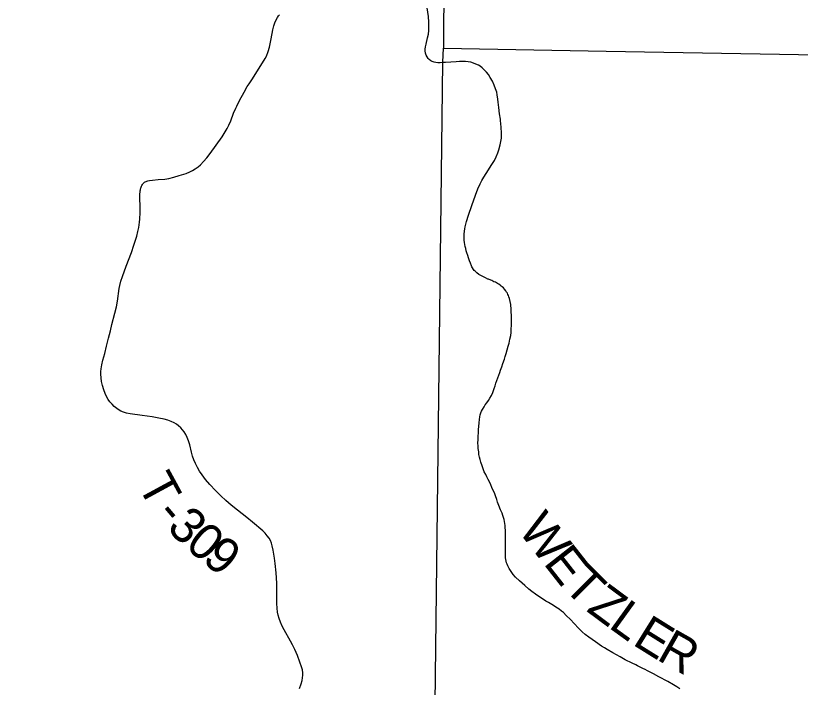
# Model space of a CAD drawing. Extents: x -10 to 158, y 8 to 33.
# Drawn here: x 127.727 to 128.969, y 27.363 to 28.427 of the extents above; entities that cross this region are included whole.
import ezdxf

# ---------------------------------------------------------------- set-up
doc = ezdxf.new("R2010")
doc.units = 0
for name, color, linetype in [('GM_X_Township_Road', 7, 'Continuous'), ('GM_X_Township_Road_Text', 7, 'Continuous'), ('GM_X_Township_Text', 7, 'Continuous')]:
    doc.layers.add(name, color=color, linetype=linetype)

msp = doc.modelspace()

# ---------------------------------------------------------------- linework, layer by layer
at = {"layer": 'GM_X_Township_Road'}
for points in [[(128.4044, 28.353), (128.4034, 28.353), (128.3993, 28.3526), (128.3956, 28.3526), (128.3925, 28.3529), (128.3895, 28.3535), (128.3865, 28.3546), (128.3843, 28.3557), (128.3819, 28.3576), (128.3801, 28.3593), (128.3784, 28.3619), (128.377, 28.3647), (128.3761, 28.3676), (128.3755, 28.3713), (128.3754, 28.3744), (128.3758, 28.3781), (128.3767, 28.3823), (128.3792, 28.3919), (128.3804, 28.398), (128.381, 28.4035), (128.3813, 28.4097), (128.3811, 28.4171), (128.3804, 28.4257), (128.3786, 28.4398)], [(128.1761, 27.3614), (128.1789, 27.3689), (128.1805, 27.3743), (128.1813, 27.3786), (128.1817, 27.3829), (128.1816, 27.3866), (128.1809, 27.3909), (128.1797, 27.3957), (128.1771, 27.4033), (128.1732, 27.4137), (128.169, 27.4233), (128.1655, 27.4305), (128.1622, 27.4365), (128.1518, 27.4542), (128.1487, 27.4602), (128.146, 27.4665), (128.1439, 27.4724), (128.1424, 27.4778), (128.1415, 27.4826), (128.1408, 27.4888), (128.1404, 27.4963), (128.1406, 27.5099), (128.1405, 27.5279), (128.1401, 27.5366), (128.1394, 27.5446), (128.1378, 27.5594), (128.1366, 27.568), (128.1347, 27.5809), (128.1332, 27.5876), (128.1319, 27.5918), (128.1302, 27.5958), (128.1281, 27.5996), (128.1253, 27.6036), (128.122, 27.6074), (128.118, 27.6113), (128.1019, 27.6248), (128.0929, 27.6322), (128.0779, 27.6442), (128.0682, 27.6519), (128.0597, 27.6591), (128.0516, 27.6668), (128.0433, 27.6752), (128.0345, 27.6848), (128.0277, 27.6928), (128.0224, 27.6997), (128.0182, 27.7059), (128.0147, 27.7117), (128.0116, 27.7178), (128.0092, 27.7235), (128.0071, 27.7294), (128.0054, 27.736), (128.0025, 27.7475), (128.0005, 27.754), (127.9985, 27.7592), (127.9964, 27.7637), (127.9938, 27.7679), (127.9912, 27.7714), (127.9882, 27.7746), (127.9849, 27.7775), (127.9814, 27.78), (127.9777, 27.7822), (127.9732, 27.7843), (127.968, 27.7863), (127.962, 27.7881), (127.9535, 27.7899), (127.9431, 27.7918), (127.9271, 27.7941), (127.9081, 27.7968), (127.9021, 27.7978), (127.8974, 27.7991), (127.8935, 27.8008), (127.8905, 27.8026), (127.8869, 27.8051), (127.883, 27.8082), (127.8795, 27.8117), (127.8762, 27.8154), (127.8734, 27.8195), (127.8709, 27.8238), (127.8686, 27.8289), (127.8664, 27.8347), (127.8645, 27.8412), (127.863, 27.8477), (127.8621, 27.8538), (127.8616, 27.8593), (127.8615, 27.8636), (127.862, 27.8678), (127.8633, 27.8743), (127.8651, 27.8815), (127.8678, 27.8922), (127.8708, 27.9036), (127.8739, 27.9163), (127.8769, 27.9283), (127.8793, 27.938), (127.8839, 27.956), (127.8863, 27.9662), (127.8879, 27.9748), (127.8909, 27.9951), (127.8918, 28), (127.8935, 28.0066), (127.8959, 28.0143), (127.902, 28.0306), (127.91, 28.0521), (127.9141, 28.0638), (127.9186, 28.078), (127.9205, 28.0852), (127.9219, 28.0919), (127.9231, 28.0999), (127.9234, 28.1049), (127.9236, 28.1079), (127.9238, 28.1123), (127.9239, 28.121), (127.9236, 28.1426), (127.9237, 28.1452), (127.9239, 28.1475), (127.9239, 28.1485), (127.9241, 28.1497), (127.9243, 28.1512), (127.9246, 28.1527), (127.9251, 28.1542), (127.9255, 28.1557), (127.9261, 28.157), (127.9268, 28.1584), (127.9276, 28.1598), (127.9284, 28.1609), (127.9293, 28.162), (127.9301, 28.1628), (127.9311, 28.1635), (127.9321, 28.1642), (127.9333, 28.1647), (127.9344, 28.1651), (127.936, 28.1656), (127.939, 28.1662), (127.9433, 28.1667), (127.9526, 28.1675), (127.9631, 28.1684), (127.9692, 28.1695), (127.9771, 28.1714), (127.986, 28.174), (127.9967, 28.1774), (128.0024, 28.1797), (128.0069, 28.182), (128.0111, 28.1846), (128.0156, 28.1879), (128.0193, 28.1912), (128.0242, 28.196), (128.0295, 28.2021), (128.0348, 28.209), (128.0443, 28.222), (128.0536, 28.2352), (128.0587, 28.243), (128.0618, 28.2483), (128.0645, 28.2539), (128.0674, 28.2607), (128.072, 28.2727), (128.0755, 28.2806), (128.077, 28.284), (128.0813, 28.2928), (128.0887, 28.3063), (128.0937, 28.3148), (128.0966, 28.3195), (128.1007, 28.3257), (128.115, 28.3482), (128.1218, 28.3594), (128.1239, 28.3631), (128.1269, 28.3706), (128.1287, 28.3772), (128.1315, 28.3905), (128.1341, 28.4046), (128.1358, 28.4112), (128.1374, 28.4159), (128.1394, 28.4205), (128.1415, 28.4243), (128.1433, 28.4268), (128.1449, 28.4287)], [(128.7786, 27.361), (128.7739, 27.3641), (128.7686, 27.3673), (128.7595, 27.3725), (128.7454, 27.3802), (128.7372, 27.3846), (128.7273, 27.3897), (128.7239, 27.3914), (128.7201, 27.3934), (128.7117, 27.3975), (128.709, 27.3989), (128.7034, 27.4016), (128.6923, 27.4072), (128.6841, 27.4115), (128.6727, 27.4178), (128.6636, 27.4232), (128.6594, 27.4258), (128.6547, 27.4288), (128.6449, 27.4354), (128.6347, 27.4426), (128.6289, 27.4471), (128.6242, 27.4511), (128.6215, 27.4537), (128.618, 27.4572), (128.6112, 27.4644), (128.6053, 27.4707), (128.5988, 27.4774), (128.5943, 27.4817), (128.5915, 27.4841), (128.5876, 27.4871), (128.5825, 27.4906), (128.5788, 27.4929), (128.5707, 27.4975), (128.5664, 27.5), (128.5611, 27.5033), (128.5555, 27.507), (128.5499, 27.511), (128.5445, 27.5152), (128.5397, 27.5191), (128.5331, 27.5246), (128.5248, 27.532), (128.5186, 27.5381), (128.5149, 27.5423), (128.5115, 27.5467), (128.5085, 27.5514), (128.5062, 27.5558), (128.505, 27.5584), (128.5043, 27.5607), (128.5036, 27.563), (128.5032, 27.5657), (128.5028, 27.5684), (128.5025, 27.5763), (128.5024, 27.5893), (128.5027, 27.6042), (128.5025, 27.6122), (128.5022, 27.6161), (128.5019, 27.6197), (128.5015, 27.6229), (128.501, 27.6259), (128.5004, 27.6291), (128.4995, 27.6325), (128.4986, 27.6354), (128.4971, 27.6395), (128.4949, 27.6446), (128.4921, 27.6515), (128.4901, 27.6567), (128.4886, 27.661), (128.4867, 27.6666), (128.4849, 27.6712), (128.4833, 27.6752), (128.4812, 27.6798), (128.4792, 27.6843), (128.477, 27.6887), (128.4751, 27.6926), (128.4728, 27.697), (128.4712, 27.7003), (128.469, 27.7047), (128.4671, 27.7093), (128.4654, 27.7142), (128.4634, 27.7202), (128.4623, 27.7241), (128.4615, 27.7281), (128.4606, 27.7324), (128.4601, 27.7365), (128.4595, 27.7415), (128.4592, 27.7456), (128.459, 27.7509), (128.4591, 27.7553), (128.4594, 27.7606), (128.4598, 27.767), (128.4599, 27.7715), (128.4603, 27.7766), (128.4608, 27.7825), (128.4613, 27.7876), (128.4619, 27.7917), (128.4627, 27.7952), (128.4634, 27.7979), (128.4646, 27.8006), (128.466, 27.8032), (128.4686, 27.8074), (128.4706, 27.8106), (128.473, 27.8141), (128.4754, 27.8177), (128.4778, 27.8214), (128.4802, 27.8258), (128.4825, 27.8304), (128.4836, 27.8334), (128.4847, 27.8369), (128.486, 27.841), (128.4875, 27.8454), (128.4906, 27.8535), (128.4937, 27.8623), (128.4949, 27.8658), (128.4968, 27.8711), (128.4984, 27.8763), (128.5008, 27.8834), (128.5021, 27.8876), (128.5035, 27.8923), (128.5053, 27.8979), (128.5069, 27.9036), (128.5083, 27.9085), (128.5097, 27.9146), (128.5108, 27.9209), (128.5115, 27.9254), (128.5118, 27.9308), (128.5121, 27.937), (128.5122, 27.9426), (128.5122, 27.9488), (128.5115, 27.9618), (128.5108, 27.9698), (128.51, 27.9747), (128.5087, 27.9795), (128.508, 27.9819), (128.5071, 27.9842), (128.5064, 27.9858), (128.5055, 27.9876), (128.5044, 27.9894), (128.5032, 27.9913), (128.5009, 27.9942), (128.4992, 27.996), (128.4973, 27.9976), (128.4958, 27.999), (128.4939, 28.0003), (128.4919, 28.0018), (128.4898, 28.0031), (128.4866, 28.0049), (128.4843, 28.0059), (128.481, 28.0075), (128.4793, 28.0083), (128.4759, 28.0097), (128.4748, 28.0101), (128.4709, 28.0118), (128.4648, 28.0149), (128.4606, 28.0174), (128.4571, 28.02), (128.4543, 28.0226), (128.4531, 28.0238), (128.4519, 28.0254), (128.4503, 28.028), (128.4495, 28.0293), (128.4488, 28.0308), (128.447, 28.0354), (128.4458, 28.0389), (128.4442, 28.0436), (128.443, 28.0471), (128.4414, 28.0517), (128.4405, 28.0547), (128.4396, 28.0583), (128.4386, 28.0618), (128.438, 28.0648), (128.4375, 28.0681), (128.4372, 28.0717), (128.437, 28.0745), (128.4369, 28.0775), (128.4369, 28.0811), (128.4375, 28.086), (128.4382, 28.0897), (128.4389, 28.0927), (128.4399, 28.0969), (128.441, 28.1011), (128.444, 28.1113), (128.4491, 28.1266), (128.455, 28.143), (128.4589, 28.1528), (128.4625, 28.1607), (128.4653, 28.1662), (128.4683, 28.1716), (128.4719, 28.1774), (128.4811, 28.1914), (128.4849, 28.1978), (128.4879, 28.2039), (128.4905, 28.2102), (128.4921, 28.2149), (128.4942, 28.2227), (128.4954, 28.2281), (128.4961, 28.233), (128.4964, 28.2374), (128.4964, 28.2423), (128.4959, 28.2498), (128.4952, 28.2571), (128.4948, 28.2602), (128.4944, 28.2632), (128.4933, 28.2718), (128.492, 28.2816), (128.4911, 28.2902), (128.4905, 28.2951), (128.4895, 28.3018), (128.4886, 28.3061), (128.487, 28.3115), (128.4847, 28.3173), (128.4818, 28.3234), (128.4785, 28.3294), (128.4754, 28.3341), (128.4723, 28.338), (128.469, 28.3416), (128.4657, 28.3445), (128.4622, 28.3471), (128.4596, 28.3487), (128.4557, 28.3506), (128.4519, 28.3521), (128.4476, 28.3534), (128.4433, 28.3541), (128.439, 28.3546), (128.4345, 28.3546), (128.4296, 28.3546), (128.4247, 28.3543), (128.416, 28.3538), (128.4074, 28.3533), (128.4044, 28.353)]]:
    msp.add_lwpolyline(points, dxfattribs=at)
at = {"layer": 'GM_X_Township_Text'}
for points in [[(126.1038, 30.3865), (126.7862, 30.3776), (127.3186, 30.3717), (127.3748, 30.3712), (127.3749, 29.9155), (127.3818, 29.8865), (127.391, 29.7447), (127.3932, 29.6834), (127.3898, 29.6674), (127.3806, 29.6412), (127.3727, 29.3597), (127.4764, 29.3589), (128.0062, 29.36), (128.408, 29.3517), (128.4072, 28.9327), (128.4042, 28.3758), (128.6622, 28.3709), (128.9974, 28.365), (129.3242, 28.3598), (129.7479, 28.3639), (130.1791, 28.3585), (130.4564, 28.3588), (130.461, 27.8534), (130.5863, 27.8482)], [(126.1038, 30.3865), (126.1038, 27.0364), (126.3333, 27.0308), (126.5452, 27.0287), (127.0949, 27.0121), (127.9467, 26.9899), (128.0604, 26.987), (128.3868, 26.9847), (128.4032, 28.3535), (128.4042, 28.3758)]]:
    msp.add_lwpolyline(points, dxfattribs=at)

# ---------------------------------------------------------------- texts
at = {"layer": 'GM_X_Township_Road_Text'}
for s, rotation, p in [('T', 298.5126, (127.9191, 27.6841)), ('-', 310.1844, (127.9465, 27.6364)), ('3', 314.2996, (127.9645, 27.6153)), ('W', 307.5312, (128.521, 27.6126)), ('0', 319.8162, (127.9934, 27.5862)), ('9', 321.2792, (128.0204, 27.5633)), ('E', 308.1791, (128.5615, 27.5599)), ('T', 314.735, (128.5924, 27.5212)), ('Z', 323.387, (128.6293, 27.485)), ('L', 324.2306, (128.6641, 27.4591)), ('E', 328.1119, (128.702, 27.432)), ('R', 330.5625, (128.7403, 27.4082))]:
    msp.add_text(s, height=0.0568, rotation=rotation, dxfattribs=at).set_placement(p)

doc.saveas('drawing.dxf')
